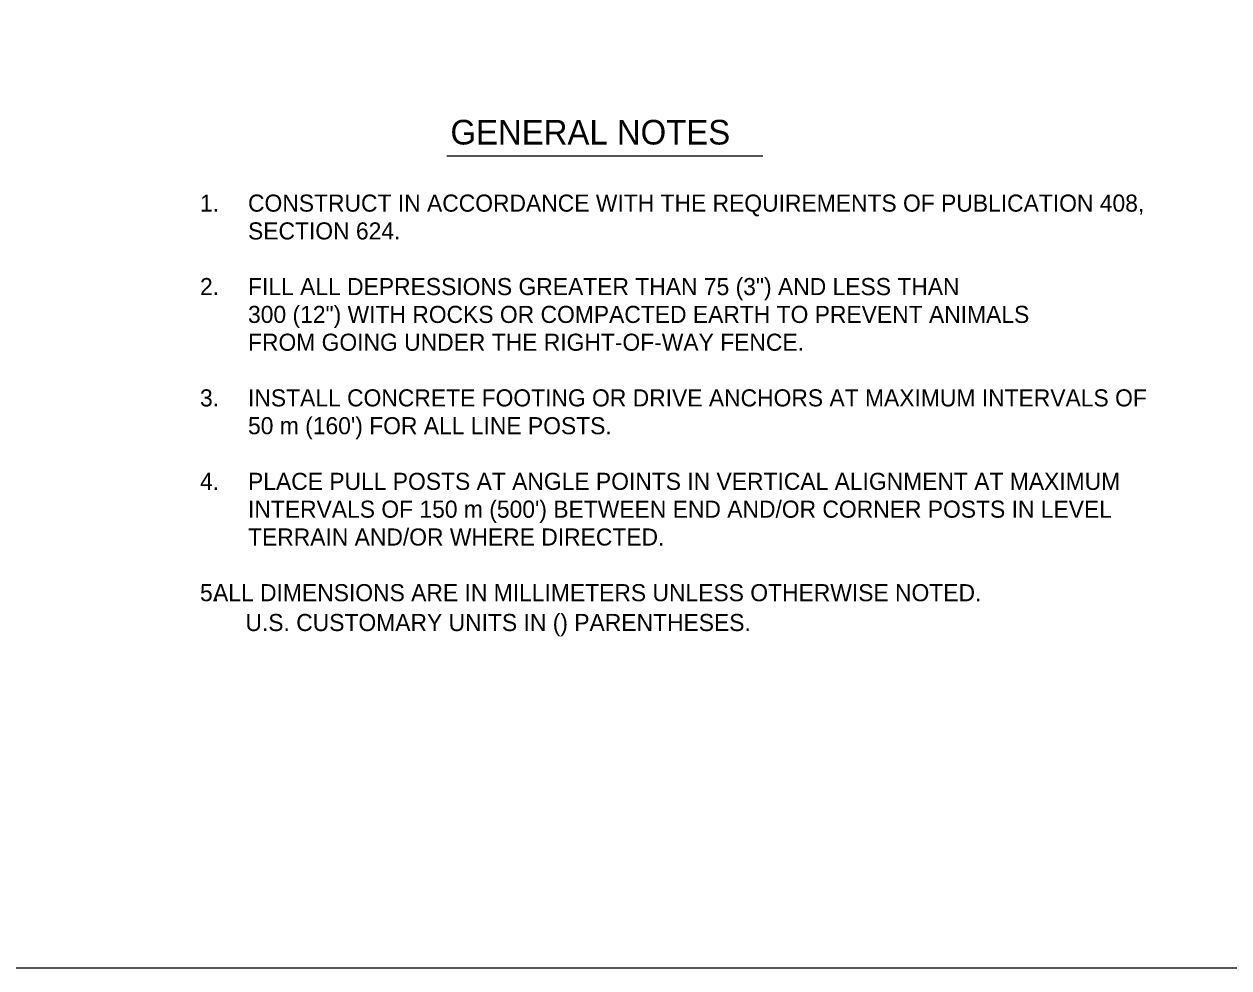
# Model space of a CAD drawing. Extents: x 13 to 918, y -903 to 879.
# Drawn here: x 317.7 to 538, y 299.9 to 472.5 of the extents above; entities that cross this region are included whole.
import ezdxf

# ---------------------------------------------------------------- set-up
doc = ezdxf.new("R2010")
doc.units = 0
for name, color, linetype in [('1', 7, 'Continuous'), ('2', 7, 'Continuous'), ('3', 7, 'Continuous'), ('40', 7, 'Continuous')]:
    doc.layers.add(name, color=color, linetype=linetype)

msp = doc.modelspace()

# ---------------------------------------------------------------- linework, layer by layer
at = {"layer": '1'}
msp.add_line((394.9725, 448.35125), (452.7855, 448.35125), dxfattribs=at)
msp.add_lwpolyline([(839.2505, 299.93025), (839.2505, 863.93025), (53.2505, 863.93025), (53.2505, 299.93025), (839.2505, 299.93025), (839.2505, 326.28925), (639.2505, 326.28925), (639.2505, 390.96675), (839.2505, 390.96675), (839.2505, 419.93025), (639.2505, 419.93025), (639.2505, 299.93025), (718.052, 299.93025), (718.052, 326.28925), (718.052, 299.93025), (795.052, 299.93025), (795.052, 326.28925), (795.052, 313.97275), (839.2505, 313.97275)], dxfattribs=at)

# ---------------------------------------------------------------- texts
at = {"layer": '2'}
msp.add_text('   ALL DIMENSIONS ARE IN MILLIMETERS UNLESS OTHERWISE NOTED.', height=3.126, dxfattribs=at).set_placement((348.75175, 366.956))
at = {"layer": '3'}
for s, height, p in [('GENERAL NOTES', 4.5, (395.65975, 450.443)), ('1.  ', 3.124999, (349.85325, 438.16975)), ('CONSTRUCT IN ACCORDANCE WITH THE REQUIREMENTS OF PUBLICATION 408,', 3.1249995, (358.6345, 438.16975)), ('SECTION 624.', 3.1249995, (358.6345, 433.08425)), ('2.  ', 3.124999, (349.85325, 422.91125)), ('FILL ALL DEPRESSIONS GREATER THAN 75 (3") AND LESS THAN', 3.1249995, (358.6345, 422.91125)), ('300 (12") WITH ROCKS OR COMPACTED EARTH TO PREVENT ANIMALS', 3.1249995, (358.6345, 417.826)), ('FROM GOING UNDER THE RIGHT-OF-WAY FENCE.', 3.1249995, (358.6345, 412.7385)), ('3.  ', 3.124999, (349.85325, 402.5655)), ('INSTALL CONCRETE FOOTING OR DRIVE ANCHORS AT MAXIMUM INTERVALS OF ', 3.1249995, (358.6345, 402.5655)), ("50 m (160') FOR ALL LINE POSTS.", 3.1249995, (358.6345, 397.48)), ('4.  ', 3.124999, (349.85325, 387.30725)), ('PLACE PULL POSTS AT ANGLE POINTS IN VERTICAL ALIGNMENT AT MAXIMUM', 3.1249995, (358.6345, 387.30725)), ("INTERVALS OF 150 m (500') BETWEEN END AND/OR CORNER POSTS IN LEVEL", 3.1249995, (358.6345, 382.21975)), ('TERRAIN AND/OR WHERE DIRECTED.', 3.1249995, (358.6345, 377.13425)), ('5.  ', 3.124999, (349.85325, 366.96125))]:
    msp.add_text(s, height=height, dxfattribs=at).set_placement(p)
at = {"layer": '40'}
msp.add_text('U.S. CUSTOMARY UNITS IN () PARENTHESES.', height=3.126, dxfattribs=at).set_placement((358.15725, 361.50325))

doc.saveas('drawing.dxf')
